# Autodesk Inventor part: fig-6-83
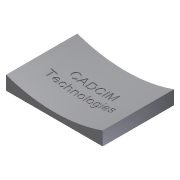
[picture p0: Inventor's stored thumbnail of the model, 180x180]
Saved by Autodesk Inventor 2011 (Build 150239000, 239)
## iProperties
Shininess: 64.0
Length Units: 11269
Angle Units: 11279
Time Units: 11290
Mass Units: 11283
Length Display Precision: 3
Angle Display Precision: 2
Compacted: True
Part Number: fig-6-83
Document SubType Name: Modeling
Created: 2002-12
Designer: deepak
Density: 1 g/cm^3
Density: 0.0
Volumn: 0.0
Area: 0.0
PropertySet Name: Model Information
Control State: 0
Master: False
Checked Out: False
Author: deepak
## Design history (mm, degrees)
sketch "Sketch1"
  geometry: L1 (-39.922, 33.786)-(30.103, 33.786); L2 (30.103, 33.786)-(30.103, -17.894); L3 (30.103, -17.894)-(-39.922, -17.894); L4 (-39.922, -17.894)-(-39.922, 33.786)
  constraints: 8 end point, 2 parallel, 1 horizontal, 1 perpendicular
extrude "Extrusion1" new body sketch "Sketch1" distance "d0" = 10; taper "d1" = 0 deg
workplane "Work Plane1"
sketch "Sketch2"
  geometry: L1 (-37.656, 15.034)-(26.28, 15.034); L2 (26.28, 15.034)-(26.28, 10.168); L3 (26.28, 10.168)-(-37.656, 10.168); L4 (-37.656, 10.168)-(-37.656, 15.034)
  constraints: 2 other
sketch "Sketch3"
  geometry: L1 (70.026, 10)-(0, 10) reference; A1 r 105 centre (35.013, 108.99) between (0, 10) and (70.026, 10)
  constraints: 2 point on circle, 1 centre point
  dimensions: "d5" = 105 radius of A1
extrude "Extrusion2" cut sketch "Sketch3" stored distance "d3" = 10; taper "d4" = 0 deg
emboss "Emboss4" sketch "Sketch2" dims "d14" = 1, "d15" = 0
body "Solid1"
other parameters: "d2" = 5
